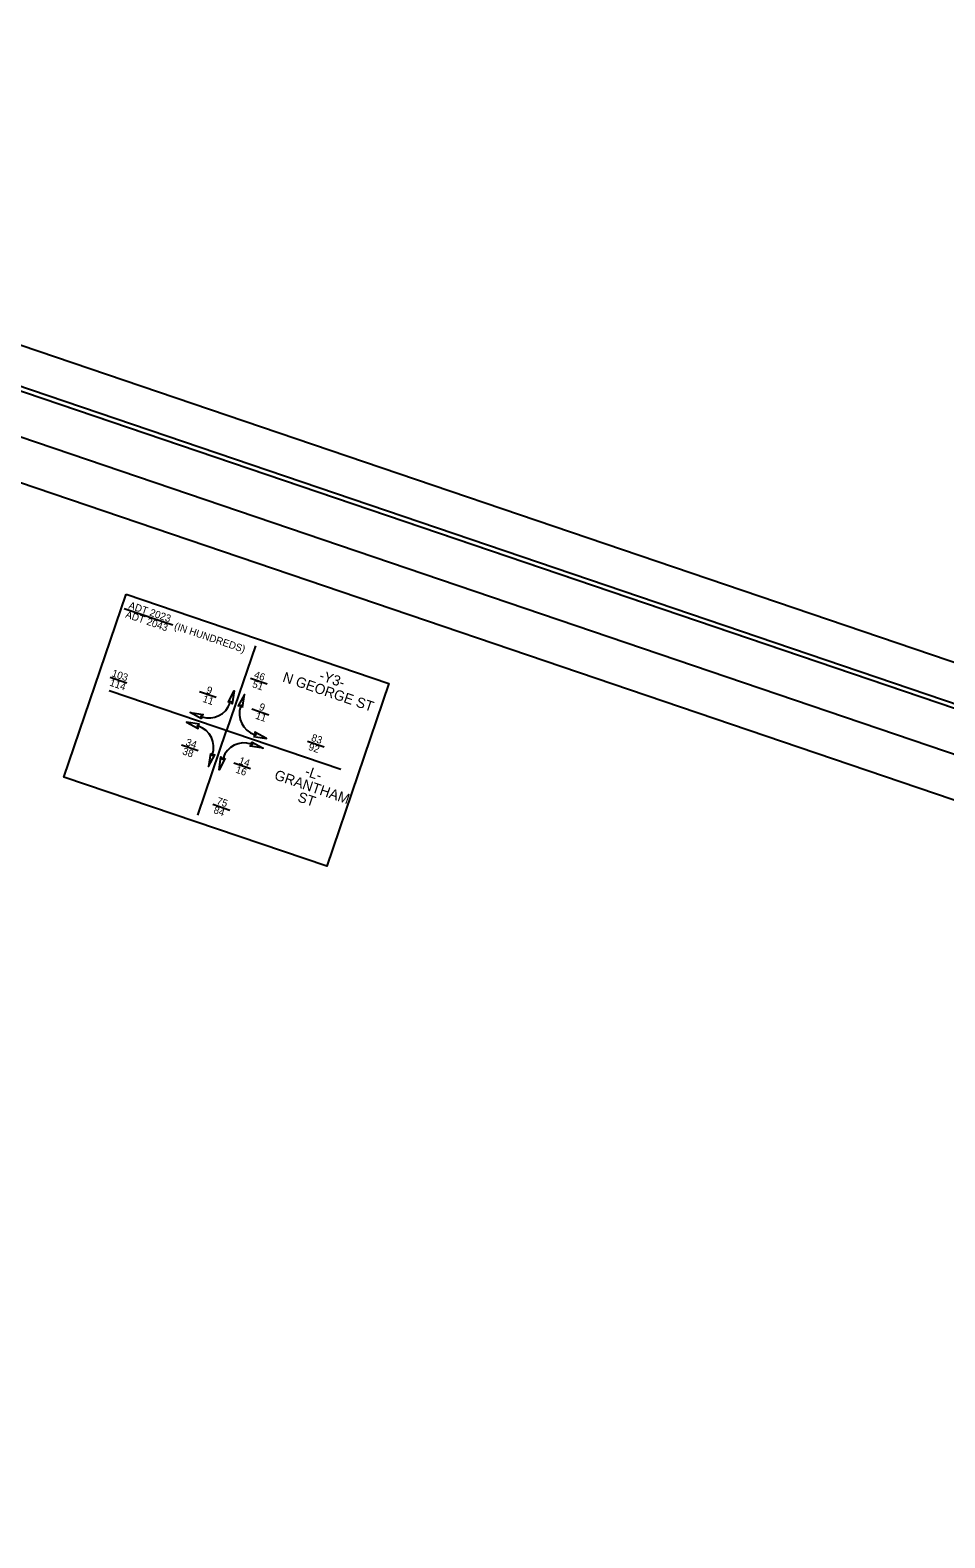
# Model space of a CAD drawing. Extents: x 2298691 to 2299860, y 598939 to 599889.
# Drawn here: x 2299227 to 2299543, y 599368 to 599889 of the extents above; entities that cross this region are included whole.
import ezdxf

# ---------------------------------------------------------------- set-up
doc = ezdxf.new("R2010")
doc.units = 0
for name, color, linetype in [('Default', 7, 'Continuous'), ('Prop DSN Text', 7, 'Continuous'), ('Scratch_Level_0', 7, 'Continuous'), ('Sheet Border Standard 30in CELL', 7, 'Continuous'), ('Sheet Layout Plan Border', 7, 'Continuous'), ('Sheet Plan Layout CELL', 7, 'Continuous'), ('Sheet Plot Border Inside CELL', 7, 'Continuous'), ('Sheet Plot Border Outside CELL', 7, 'Continuous')]:
    doc.layers.add(name, color=color, linetype=linetype)

msp = doc.modelspace()

# ---------------------------------------------------------------- linework, layer by layer
at = {"layer": 'Default'}
for points in [[(2299295.54, 599656.61), (2299297.69, 599660.64), (2299297.01, 599656.11), (2299296.42, 599656.92)], [(2299300.54, 599654.91), (2299301.29, 599659.41), (2299299.07, 599655.41), (2299300.03, 599655.69)], [(2299286.42, 599650.95), (2299282.39, 599653.1), (2299286.92, 599652.43), (2299286.11, 599651.83)], [(2299285.71, 599649.07), (2299281.21, 599649.82), (2299285.21, 599647.59), (2299284.93, 599648.55)], [(2299304.33, 599644.87), (2299308.83, 599644.12), (2299304.83, 599646.34), (2299305.11, 599645.38)], [(2299303.68, 599642.96), (2299307.71, 599640.82), (2299303.18, 599641.49), (2299303.99, 599642.08)], [(2299289.5, 599639.03), (2299288.75, 599634.52), (2299290.97, 599638.52), (2299290.01, 599638.25)], [(2299294.56, 599637.31), (2299292.42, 599633.28), (2299293.09, 599637.81), (2299293.68, 599637)]]:
    msp.add_lwpolyline(points, close=True, dxfattribs=at)
for centre, start, end in [((2299289, 599658.98), 251.2405, 341.2405), ((2299307.17, 599652.8), 161.2404, 251.2404), ((2299282.87, 599641.13), 341.2404, 71.2404), ((2299301.1, 599634.94), 71.2405, 161.2405)]:
    msp.add_arc(centre, 7.69, start, end, dxfattribs=at)
at = {"layer": 'Prop DSN Text'}
for p, q in [((2299259.61, 599689.14), (2299276.46, 599683.42)), ((2299304.99, 599676.23), (2299295.05, 599646.96)), ((2299254.49, 599660.73), (2299334.58, 599633.53)), ((2299254.75, 599665.34), (2299260.55, 599663.37)), ((2299303.3, 599665.04), (2299309.1, 599663.07)), ((2299285.64, 599660.36), (2299291.44, 599658.39)), ((2299303.82, 599654.36), (2299309.62, 599652.39)), ((2299285.11, 599617.68), (2299295.05, 599646.96)), ((2299279.4, 599641.99), (2299285.2, 599640.02)), ((2299323.02, 599643.28), (2299328.82, 599641.31)), ((2299297.49, 599635.74), (2299303.3, 599633.77)), ((2299290.33, 599621.41), (2299296.13, 599619.44))]:
    msp.add_line(p, q, dxfattribs=at)
msp.add_lwpolyline([(2299260.27, 599694.07), (2299351.16, 599663.2), (2299329.68, 599599.98), (2299238.8, 599630.85)], close=True, dxfattribs=at)
at = {"layer": 'Scratch_Level_0'}
msp.add_lwpolyline([(2299002.4, 599823.52), (2298809.46, 599255.41), (2299633.24, 598975.62), (2299795.1, 599452.24), (2299681.46, 599490.84), (2299712.53, 599582.33)], close=True, dxfattribs=at)
at = {"layer": 'Sheet Border Standard 30in CELL'}
msp.add_lwpolyline([(2299845.21, 599553.11), (2298993.02, 599842.55), (2298790.42, 599246.02), (2299642.61, 598956.58)], close=True, dxfattribs=at)
at = {"layer": 'Sheet Layout Plan Border'}
msp.add_lwpolyline([(2299035.49, 599796.46), (2298855.43, 599254), (2299623.37, 598993.18), (2299776.1, 599442.85), (2299690.83, 599471.81), (2299700.48, 599500.22), (2299721.92, 599563.32), (2299035.49, 599796.46)], close=True, dxfattribs=at)
at = {"layer": 'Sheet Plan Layout CELL'}
msp.add_lwpolyline([(2298993.02, 599842.55), (2298790.44, 599246.03), (2299642.62, 598956.59), (2299806.65, 599439.6), (2299693.01, 599478.2), (2299731.56, 599591.71)], close=True, dxfattribs=at)
at = {"layer": 'Sheet Plot Border Inside CELL'}
msp.add_lwpolyline([(2299852.81, 599552.15), (2298906.02, 599873.72), (2298702.43, 599274.29), (2299649.22, 598952.72)], close=True, dxfattribs=at)
at = {"layer": 'Sheet Plot Border Outside CELL'}
msp.add_lwpolyline([(2299859.69, 599564.04), (2298902.97, 599888.98), (2298690.72, 599264.04), (2299647.44, 598939.1)], close=True, dxfattribs=at)

# ---------------------------------------------------------------- texts
at = {"layer": 'Prop DSN Text'}
for s, height, p in [('ADT 2043', 2.52, (2299259.87, 599686.04)), ('ADT 2023', 2.52, (2299260.93, 599689.17)), ('(IN HUNDREDS)', 2.52, (2299276.73, 599681.99)), ('103', 2.52, (2299255.13, 599665.73)), ('46', 2.52, (2299304.3, 599665.22)), ('N GEORGE ST', 3.528, (2299314.16, 599663.92)), ('-Y3-', 3.528, (2299326.79, 599664.51)), ('114', 2.52, (2299254.37, 599662.5)), ('9', 2.52, (2299287.81, 599659.93)), ('51', 2.52, (2299303.7, 599661.93)), ('11', 2.52, (2299286.54, 599656.87)), ('9', 2.52, (2299306.06, 599654.12)), ('11', 2.52, (2299304.79, 599651.07)), ('83', 2.52, (2299324.09, 599643.44)), ('38', 2.52, (2299279.55, 599638.76)), ('34', 2.52, (2299280.68, 599641.87)), ('92', 2.52, (2299323.11, 599640.28)), ('14', 2.52, (2299299.06, 599635.52)), ('16', 2.52, (2299297.94, 599632.41)), ('GRANTHAM', 3.528, (2299311.29, 599630.11)), ('-L-', 3.528, (2299321.83, 599631.41)), (' ST', 3.528, (2299318.09, 599622.91)), ('84', 2.52, (2299290.31, 599618.45)), ('75', 2.52, (2299291.36, 599621.58))]:
    msp.add_text(s, height=height, rotation=341.2404, dxfattribs=at).set_placement(p)

doc.saveas('drawing.dxf')
